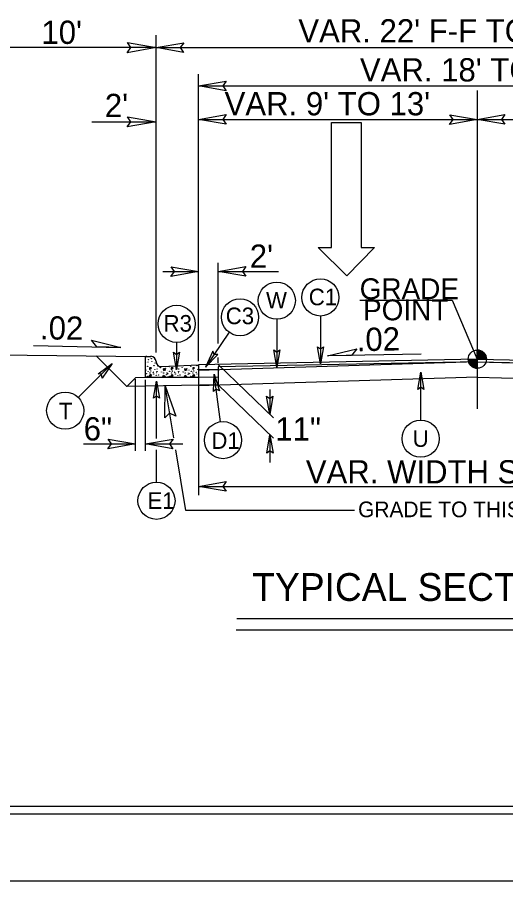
# Model space of a CAD drawing. Extents: x 958711 to 962106, y 831169 to 840840.
# Drawn here: x 959372.3 to 959536.1, y 834842.4 to 835132 of the extents above; entities that cross this region are included whole.
import ezdxf

# ---------------------------------------------------------------- set-up
doc = ezdxf.new("R2010")
doc.units = 0
for name, color, linetype in [('Default', 7, 'Continuous'), ('Old_Level_1', 7, 'Continuous'), ('Old_Level_11', 7, 'Continuous'), ('Old_Level_3', 7, 'Continuous'), ('Prop Dimension Text', 7, 'Continuous'), ('Prop Lane Arrow CELL', 7, 'Continuous'), ('Sheet Plot Border Inside CELL', 7, 'Continuous'), ('Sheet Plot Border Outside CELL', 7, 'Continuous'), ('Sheet Typical CELL', 7, 'Continuous'), ('Typical ID Circle CELL', 7, 'Continuous'), ('Typical Terminator CELL', 7, 'Continuous'), ('Typical Text Grade Point CELL', 7, 'Continuous'), ('Typical Text ID Circle CELL', 7, 'Continuous')]:
    doc.layers.add(name, color=color, linetype=linetype)

# ---------------------------------------------------------------- blocks, each defined once
blk = doc.blocks.new('Lane Arrow Through')
at = {"layer": 'Prop Lane Arrow CELL'}
for p, q in [((-3.15, 1.6), (-3.15, 3.1)), ((-3.15, 3.1), (0, 0)), ((-17.15, 1.6), (-3.15, 1.6)), ((-17.15, -1.7), (-17.15, 1.6)), ((0, 0), (-3.15, -3.2)), ((-3.15, -1.7), (-17.15, -1.7)), ((-3.15, -3.2), (-3.15, -1.7))]:
    blk.add_line(p, q, dxfattribs=at)

msp = doc.modelspace()

# ---------------------------------------------------------------- linework, layer by layer
at = {"layer": 'Default'}
msp.add_line((959526.54, 835107.49), (959526.54, 835000.68), dxfattribs=at)
at = {"layer": 'Old_Level_1'}
for p, q in [((959418.82, 835019.61), (959418.82, 835126.07)), ((959418.82, 835121.85), (959352.27, 835121.85)), ((959418.82, 835121.85), (959634.32, 835121.85)), ((959433.06, 835016.63), (959433.06, 835112.89)), ((959433.06, 835108.99), (959620.02, 835108.99)), ((959397.31, 835096.99), (959418.82, 835096.99)), ((959433.06, 835097.75), (959526.54, 835097.75)), ((959526.54, 835097.75), (959620.02, 835097.75)), ((959439.67, 835022.62), (959439.67, 835049.67)), ((959421.13, 835046.74), (959433.06, 835046.74)), ((959439.67, 835046.74), (959459.9, 835046.74)), ((959377.73, 835021.89), (959406.95, 835021.3)), ((959526.54, 835017.34), (959526.54, 835020.4)), ((959352.27, 835018.94), (959415.26, 835018.3)), ((959408.99, 835008.14), (959398.67, 835018.47)), ((959526.54, 835017.35), (959433.06, 835015.46)), ((959439.67, 835016.15), (959439.67, 835017.94)), ((959507.77, 835019.06), (959476.34, 835018.42)), ((959523.48, 835017.34), (959526.54, 835017.34)), ((959526.54, 835017.35), (959620.02, 835015.46)), ((959529.6, 835017.34), (959526.54, 835017.34)), ((959526.54, 835014.29), (959526.54, 835017.34)), ((959526.54, 835017.34), (959526.54, 835014.29)), ((959526.52, 835016.48), (959433.06, 835013.55)), ((959526.56, 835016.48), (959439.67, 835014.73)), ((959439.67, 835015.59), (959458.14, 834997.66)), ((959439.67, 835014.73), (959439.67, 835008.77)), ((959526.53, 835016.48), (959613.48, 835014.73)), ((959526.57, 835016.48), (959620.02, 835013.55)), ((959411.96, 835011.11), (959408.99, 835008.14)), ((959415.26, 835011.18), (959411.96, 835011.11)), ((959439.67, 835013.86), (959433.06, 835013.73)), ((959433.06, 835013.55), (959433.06, 835008.42)), ((959526.54, 835011.35), (959433.06, 835008.42)), ((959439.67, 835011.31), (959433.06, 835011.18)), ((959526.54, 835011.35), (959620.02, 835008.42)), ((959439.67, 835008.77), (959408.99, 835008.14)), ((959411.96, 834986.62), (959411.96, 835010.67)), ((959415.26, 834986.62), (959415.26, 835010.38)), ((959424.73, 834991.02), (959421.86, 835008.4)), ((959433.06, 835008.42), (959433.06, 834971.78)), ((959439.67, 835008.77), (959458.14, 834990.84)), ((959456.93, 835007.2), (959456.93, 834998.84)), ((959456.99, 834991.94), (959456.99, 834982.72)), ((959394.42, 834988.92), (959411.96, 834988.92)), ((959415.26, 834988.92), (959427.79, 834988.92)), ((959428.75, 834966.64), (959425.4, 834986.92)), ((959433.06, 834974.66), (959620.02, 834974.66)), ((959485.38, 834966.64), (959428.75, 834966.64)), ((959613.61, 834930.23), (959445.91, 834930.23)), ((959613.32, 834926.42), (959445.63, 834926.42))]:
    msp.add_line(p, q, dxfattribs=at)
for points in [[(959526.58, 835020.4), (959526.58, 835020.4), (959526.58, 835017.34)], [(959526.64, 835020.4), (959526.64, 835017.34)], [(959526.7, 835020.4), (959526.7, 835017.34)], [(959526.76, 835020.39), (959526.76, 835017.34)], [(959526.83, 835020.39), (959526.83, 835017.34)], [(959526.89, 835020.39), (959526.89, 835017.34)], [(959526.95, 835020.37), (959526.95, 835017.34)], [(959527.01, 835020.37), (959527.01, 835017.34)], [(959527.06, 835020.35), (959527.06, 835017.34)], [(959527.12, 835020.35), (959527.12, 835017.34)], [(959527.19, 835020.34), (959527.19, 835017.34)], [(959527.25, 835020.32), (959527.25, 835017.34)], [(959527.31, 835020.3), (959527.31, 835017.34)], [(959527.37, 835020.28), (959527.37, 835017.34)], [(959527.44, 835020.27), (959527.44, 835017.34)], [(959527.49, 835020.24), (959527.49, 835017.34)], [(959527.56, 835020.23), (959527.55, 835017.34)], [(959527.61, 835020.21), (959527.61, 835017.34)], [(959527.68, 835020.19), (959527.68, 835017.34)], [(959527.74, 835020.16), (959527.74, 835017.34)], [(959527.8, 835020.14), (959527.8, 835017.34)], [(959527.87, 835020.1), (959527.87, 835017.34)], [(959527.92, 835020.08), (959527.92, 835017.34)], [(959527.98, 835020.05), (959527.98, 835017.34)], [(959528.04, 835020.02), (959528.04, 835017.34)], [(959528.11, 835019.98), (959528.11, 835017.34)], [(959528.17, 835019.94), (959528.17, 835017.34)], [(959528.23, 835019.9), (959528.23, 835017.34)], [(959528.29, 835019.85), (959528.29, 835017.34)], [(959528.34, 835019.82), (959528.34, 835017.34)], [(959523.51, 835017.34), (959523.51, 835017.02)], [(959523.57, 835017.34), (959523.57, 835016.65)], [(959523.63, 835017.34), (959523.63, 835016.43)], [(959523.69, 835017.34), (959523.69, 835016.25)], [(959523.76, 835017.34), (959523.76, 835016.11)], [(959523.82, 835017.34), (959523.82, 835015.98)], [(959523.87, 835017.34), (959523.87, 835015.86)], [(959523.93, 835017.34), (959523.93, 835015.75)], [(959524, 835017.34), (959524, 835015.67)], [(959524.06, 835017.34), (959524.06, 835015.57)], [(959524.12, 835017.34), (959524.12, 835015.48)], [(959524.18, 835017.34), (959524.18, 835015.41)], [(959524.24, 835017.34), (959524.24, 835015.35)], [(959524.3, 835017.34), (959524.3, 835015.27)], [(959524.36, 835017.34), (959524.36, 835015.2)], [(959524.43, 835017.34), (959524.43, 835015.15)], [(959524.49, 835017.34), (959524.49, 835015.1)], [(959524.55, 835017.34), (959524.55, 835015.03)], [(959524.61, 835017.34), (959524.61, 835014.99)], [(959524.68, 835017.34), (959524.68, 835014.93)], [(959524.73, 835017.34), (959524.73, 835014.89)], [(959524.79, 835017.34), (959524.79, 835014.84)], [(959524.85, 835017.34), (959524.85, 835014.81)], [(959524.91, 835017.34), (959524.91, 835014.75)], [(959524.98, 835017.34), (959524.98, 835014.72)], [(959525.04, 835017.34), (959525.04, 835014.68)], [(959525.1, 835017.34), (959525.1, 835014.65)], [(959525.15, 835017.34), (959525.15, 835014.63)], [(959525.22, 835017.34), (959525.22, 835014.59)], [(959525.28, 835017.34), (959525.28, 835014.56)], [(959525.34, 835017.34), (959525.34, 835014.54)], [(959525.4, 835017.34), (959525.4, 835014.5)], [(959525.47, 835017.34), (959525.47, 835014.49)], [(959525.53, 835017.34), (959525.53, 835014.47)], [(959525.58, 835017.34), (959525.58, 835014.44)], [(959525.65, 835017.34), (959525.65, 835014.43)], [(959525.71, 835017.34), (959525.71, 835014.4)], [(959525.77, 835017.34), (959525.77, 835014.39)], [(959525.83, 835017.34), (959525.83, 835014.38)], [(959525.89, 835017.34), (959525.89, 835014.36)], [(959525.96, 835017.34), (959525.96, 835014.34)], [(959526.01, 835017.34), (959526.01, 835014.34)], [(959526.07, 835017.34), (959526.07, 835014.33)], [(959526.13, 835017.34), (959526.13, 835014.31)], [(959526.2, 835017.34), (959526.2, 835014.31)], [(959526.26, 835017.34), (959526.26, 835014.31)], [(959526.32, 835017.34), (959526.32, 835014.29)], [(959526.38, 835017.34), (959526.38, 835014.29)], [(959526.44, 835017.34), (959526.44, 835014.29)], [(959526.5, 835017.34), (959526.5, 835014.29), (959526.5, 835014.29)], [(959528.41, 835019.77), (959528.41, 835017.34)], [(959528.47, 835019.72), (959528.47, 835017.34)], [(959528.53, 835019.68), (959528.53, 835017.34)], [(959528.59, 835019.61), (959528.59, 835017.34)], [(959528.66, 835019.55), (959528.66, 835017.34)], [(959528.72, 835019.49), (959528.72, 835017.34)], [(959528.78, 835019.43), (959528.78, 835017.34)], [(959528.84, 835019.37), (959528.84, 835017.34)], [(959528.9, 835019.3), (959528.9, 835017.34)], [(959528.96, 835019.21), (959528.96, 835017.34)], [(959529.03, 835019.14), (959529.03, 835017.34)], [(959529.09, 835019.05), (959529.09, 835017.34)], [(959529.15, 835018.96), (959529.15, 835017.34)], [(959529.2, 835018.85), (959529.2, 835017.34)], [(959529.26, 835018.75), (959529.26, 835017.34)], [(959529.32, 835018.6), (959529.32, 835017.34)], [(959529.39, 835018.46), (959529.39, 835017.34)], [(959529.45, 835018.3), (959529.45, 835017.34)], [(959529.51, 835018.09), (959529.51, 835017.34)], [(959529.57, 835017.78), (959529.57, 835017.34)]]:
    msp.add_lwpolyline(points, dxfattribs=at)
msp.add_circle((959526.55, 835017.35), 3.06, dxfattribs=at)
for start, end in [(359.9905, 89.9905), (179.9905, 269.9905)]:
    msp.add_arc((959526.55, 835017.35), 3.06, start, end, dxfattribs=at)
at = {"layer": 'Old_Level_11'}
for p, q in [((959398.95, 835021.46), (959397.21, 835023.72)), ((959397.21, 835023.72), (959406.95, 835021.3)), ((959406.95, 835021.3), (959398.95, 835021.46)), ((959476.34, 835018.42), (959486.09, 835020.85)), ((959486.09, 835020.85), (959484.36, 835018.58)), ((959484.36, 835018.58), (959476.34, 835018.42))]:
    msp.add_line(p, q, dxfattribs=at)
for points in [[(959409.22, 835123.51), (959418.82, 835121.85), (959409.16, 835120.14), (959410.39, 835121.85)], [(959409.22, 835098.65), (959418.82, 835096.99), (959409.16, 835095.27), (959410.39, 835096.99)], [(959421.77, 834997.68), (959421.86, 835008.4), (959425.43, 834998.21), (959423.37, 834999.25)]]:
    msp.add_lwpolyline(points, close=True, dxfattribs=at)
at = {"layer": 'Old_Level_3'}
for p, q in [((959415.26, 835014.74), (959415.26, 835018)), ((959415.57, 835018.3), (959417.05, 835018.3)), ((959415.26, 835011.18), (959415.26, 835014.74)), ((959416.63, 835014.49), (959416.63, 835013.87)), ((959417.26, 835014.46), (959416.63, 835014.49)), ((959416.63, 835013.87), (959417.26, 835014.46)), ((959418.97, 835016.11), (959418.85, 835015.95)), ((959418.85, 835015.95), (959419.01, 835015.99)), ((959420.67, 835014.84), (959433.06, 835015.46)), ((959420.67, 835014.84), (959420.67, 835014.84)), ((959421.16, 835014.06), (959421.26, 835013.54)), ((959422.05, 835013.81), (959421.16, 835014.06)), ((959423.86, 835014.49), (959423.86, 835013.87)), ((959424.49, 835014.46), (959423.86, 835014.49)), ((959423.86, 835013.87), (959424.49, 835014.46)), ((959428.39, 835014.06), (959428.49, 835013.54)), ((959429.28, 835013.81), (959428.39, 835014.06)), ((959431.09, 835014.49), (959431.09, 835013.87)), ((959431.71, 835014.46), (959431.09, 835014.49)), ((959431.09, 835013.87), (959431.71, 835014.46)), ((959433.06, 835015.46), (959433.06, 835011.18)), ((959433.06, 835011.18), (959415.26, 835011.18)), ((959416.54, 835011.59), (959417.04, 835012.29)), ((959417.22, 835011.63), (959416.54, 835011.59)), ((959417.04, 835012.29), (959417.22, 835011.63)), ((959420.96, 835011.3), (959421.32, 835011.96)), ((959421.92, 835011.53), (959420.96, 835011.3)), ((959421.26, 835013.54), (959422.05, 835013.81)), ((959421.32, 835011.96), (959421.92, 835011.53)), ((959423.77, 835011.59), (959424.26, 835012.29)), ((959424.45, 835011.63), (959423.77, 835011.59)), ((959424.26, 835012.29), (959424.45, 835011.63)), ((959428.19, 835011.3), (959428.55, 835011.96)), ((959429.15, 835011.53), (959428.19, 835011.3)), ((959428.49, 835013.54), (959429.28, 835013.81)), ((959428.55, 835011.96), (959429.15, 835011.53)), ((959430.99, 835011.59), (959431.48, 835012.29)), ((959431.68, 835011.63), (959430.99, 835011.59)), ((959431.48, 835012.29), (959431.68, 835011.63))]:
    msp.add_line(p, q, dxfattribs=at)
for centre in [(959416.31, 835017.14), (959417.23, 835017.54), (959418.42, 835017.4), (959415.32, 835016.44), (959416.01, 835014.96), (959416.14, 835016.35), (959417.4, 835016.54), (959418.09, 835015.16), (959418.39, 835013.97), (959418.45, 835016.01), (959419.18, 835014.03), (959419.28, 835015.12), (959420.34, 835014.46), (959421.89, 835014.3), (959425.61, 835013.97), (959426.41, 835014.03), (959427.56, 835014.46), (959429.12, 835014.3), (959430.46, 835014.96), (959432.54, 835015.16), (959432.84, 835013.97), (959415.42, 835013.67), (959415.46, 835011.33), (959415.55, 835012.52), (959416.01, 835011.59), (959416.17, 835013.24), (959416.73, 835012.75), (959417, 835013.34), (959417.86, 835012.98), (959418.02, 835012.39), (959418.88, 835011.89), (959419.05, 835012.88), (959419.15, 835013.17), (959419.61, 835012.06), (959420.63, 835013.01), (959421.33, 835012.72), (959422.35, 835012.16), (959422.45, 835012.72), (959422.65, 835013.67), (959422.68, 835011.33), (959422.77, 835012.52), (959423.24, 835011.59), (959423.4, 835013.24), (959423.96, 835012.75), (959424.23, 835013.34), (959425.09, 835012.98), (959425.25, 835012.39), (959426.11, 835011.89), (959426.28, 835012.88), (959426.37, 835013.17), (959426.84, 835012.06), (959427.86, 835013.01), (959428.56, 835012.72), (959429.58, 835012.16), (959429.68, 835012.72), (959429.88, 835013.67), (959429.91, 835011.33), (959430, 835012.52), (959430.46, 835011.59), (959430.63, 835013.24), (959431.19, 835012.75), (959431.45, 835013.34), (959432.31, 835012.98), (959432.48, 835012.39)]:
    msp.add_circle(centre, 0.0464, dxfattribs=at)
for centre, radius, start, end in [((959415.57, 835018), 0.309, 90, 180), ((959415.46, 835018.23), 0.0464, 259.6531, 10.3469), ((959417.04, 835016.53), 1.78, 1.0734, 90), ((959420.58, 835016.6), 1.76, 181.0734, 272.8624), ((959423.24, 835014.96), 0.0464, 167.7795, 17.938), ((959426.51, 835015.12), 0.0464, 169.8374, 15.8801), ((959415.22, 835012.72), 0.0464, 330.4173, 29.5827)]:
    msp.add_arc(centre, radius, start, end, dxfattribs=at)
at = {"layer": 'Sheet Plot Border Inside CELL'}
msp.add_lwpolyline([(960390.3, 835919.97), (958723.8, 835919.97), (958723.8, 834864.87), (960390.3, 834864.87)], close=True, dxfattribs=at)
at = {"layer": 'Sheet Plot Border Outside CELL'}
msp.add_lwpolyline([(960394.8, 835942.42), (958710.8, 835942.42), (958710.8, 834842.42), (960394.8, 834842.42)], close=True, dxfattribs=at)
at = {"layer": 'Sheet Typical CELL'}
msp.add_lwpolyline([(960377.8, 835917.42), (958877.8, 835917.42), (958877.8, 834867.42), (960377.8, 834867.42)], close=True, dxfattribs=at)
at = {"layer": 'Typical ID Circle CELL'}
for p, q in [((959473.93, 835031.83), (959473.93, 835015.75)), ((959459.3, 835030.76), (959459.3, 835014.67)), ((959443.34, 835026.36), (959435.4, 835014.71)), ((959425.71, 835022.98), (959425.71, 835013.89)), ((959392.74, 835004.48), (959404.12, 835015.85)), ((959440.46, 834996.37), (959438.34, 835012.31)), ((959507.57, 834996.91), (959507.57, 835012.99)), ((959418.94, 834990.78), (959418.94, 835010.02)), ((959418.94, 834976.08), (959418.94, 834986.9))]:
    msp.add_line(p, q, dxfattribs=at)
for centre in [(959459.3, 835036.98), (959473.93, 835038.06), (959446.98, 835031.41), (959425.71, 835029.21), (959388.34, 835000.08), (959507.57, 834990.68), (959441.28, 834990.2), (959418.94, 834969.86)]:
    msp.add_circle(centre, 6.23, dxfattribs=at)
at = {"layer": 'Typical Terminator CELL'}
for points in [[(959428.05, 835120.26), (959418.82, 835121.85), (959428.1, 835123.49), (959426.92, 835121.85)], [(959442.29, 835107.41), (959433.06, 835108.99), (959442.34, 835110.63), (959441.16, 835108.99)], [(959442.29, 835096.16), (959433.06, 835097.75), (959442.34, 835099.39), (959441.16, 835097.75)], [(959517.32, 835099.34), (959526.54, 835097.75), (959517.27, 835096.11), (959518.45, 835097.75)], [(959535.77, 835096.16), (959526.54, 835097.75), (959535.82, 835099.39), (959534.64, 835097.75)], [(959423.84, 835048.33), (959433.06, 835046.74), (959423.79, 835045.11), (959424.97, 835046.74)], [(959448.89, 835045.16), (959439.67, 835046.74), (959448.94, 835048.38), (959447.76, 835046.74)], [(959437.82, 835020.03), (959435.4, 835014.71), (959439.51, 835018.92), (959438.25, 835018.89)], [(959460.29, 835020.44), (959459.3, 835014.67), (959458.28, 835020.47), (959459.3, 835019.73)], [(959474.92, 835021.51), (959473.93, 835015.75), (959472.91, 835021.54), (959473.93, 835020.8)], [(959426.7, 835019.65), (959425.71, 835013.89), (959424.69, 835019.68), (959425.71, 835018.95)], [(959399.34, 835012.48), (959404.12, 835015.85), (959400.75, 835011.03), (959400.54, 835012.27)], [(959438.12, 835006.47), (959438.34, 835012.31), (959440.12, 835006.7), (959439.01, 835007.3)], [(959506.58, 835007.23), (959507.57, 835012.99), (959508.59, 835007.2), (959507.57, 835007.93)], [(959417.95, 835004.26), (959418.94, 835010.02), (959419.97, 835004.23), (959418.94, 835004.96)], [(959457.97, 835004.9), (959456.93, 834998.84), (959455.85, 835004.94), (959456.93, 835004.16)], [(959455.95, 834985.87), (959456.99, 834991.94), (959458.07, 834985.84), (959456.99, 834986.62)], [(959402.74, 834990.51), (959411.96, 834988.92), (959402.69, 834987.28), (959403.87, 834988.92)], [(959424.48, 834987.33), (959415.26, 834988.92), (959424.54, 834990.56), (959423.36, 834988.92)], [(959442.29, 834973.07), (959433.06, 834974.66), (959442.34, 834976.3), (959441.16, 834974.66)]]:
    msp.add_lwpolyline(points, close=True, dxfattribs=at)
at = {"layer": 'Typical Text Grade Point CELL'}
for p, q in [((959487.1, 835037.12), (959518.14, 835037.12)), ((959518.14, 835037.12), (959526.54, 835017.34))]:
    msp.add_line(p, q, dxfattribs=at)

# ---------------------------------------------------------------- block references
at = {"layer": 'Old_Level_1', "xscale": 3, "yscale": 3, "rotation": -90.00000000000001}
msp.add_blockref('Lane Arrow Through', (959482.75, 835045.31), dxfattribs=at)

# ---------------------------------------------------------------- texts
at = {"layer": 'Old_Level_1'}
for s, height, p in [("VAR. 22' F-F TO 30' F-F", 7.8009, (959466.52, 835123.57)), ('GRADE TO THIS LINE', 5.2473, (959486.56, 834964.35)), ('TYPICAL SECTION NO. 12', 9.3239, (959451.08, 834936.27))]:
    msp.add_text(s, height=height, dxfattribs=at).set_placement(p)
at = {"layer": 'Old_Level_11'}
for s, height, p in [('GRADE', 7, (959487.1, 835037.46)), ('POINT', 7, (959488.23, 835030.39)), ('11"', 7.801, (959458.81, 834990.07))]:
    msp.add_text(s, height=height, dxfattribs=at).set_placement(p)
at = {"layer": 'Old_Level_3'}
for s, p in [("10'", (959380.37, 835123.09)), ("2'", (959401.64, 835098.55))]:
    msp.add_text(s, height=7.801, dxfattribs=at).set_placement(p)
msp.add_text('.02', height=7.801, rotation=359.4336, dxfattribs=at).set_placement((959379.87, 835023.98))
at = {"layer": 'Prop Dimension Text'}
for s, height, rotation, p in [("VAR. 18' TO 26'", 7.8009, 0, (959487.18, 835110.5)), ("VAR. 9' TO 13'", 7.8009, 0, (959441.8, 835099.13)), ("2'", 7.801, 0, (959450.24, 835048)), ('.02', 7.801, 1.1839, (959486.2, 835020)), ('6"', 7.801, 0, (959394.54, 834990.08)), ('VAR. WIDTH SEE PLANS', 7.8009, 0, (959469.03, 834975.67))]:
    msp.add_text(s, height=height, rotation=rotation, dxfattribs=at).set_placement(p)
at = {"layer": 'Typical Text ID Circle CELL'}
for s, height, p in [('C1', 5.572, (959470.02, 835035.43)), ('W', 5.57, (959455.68, 835034.35)), ('C3', 5.572, (959442.17, 835029.09)), ('R3', 5.572, (959421.33, 835026.58)), ('D1', 5.572, (959437.35, 834987.26)), ('U', 5.57, (959504.86, 834987.94)), ('E1', 5.572, (959415.91, 834967.12))]:
    msp.add_text(s, height=height, dxfattribs=at).set_placement(p)
msp.add_text('T', height=5.57, rotation=360, dxfattribs=at).set_placement((959386.19, 834997.18))

doc.saveas('drawing.dxf')
